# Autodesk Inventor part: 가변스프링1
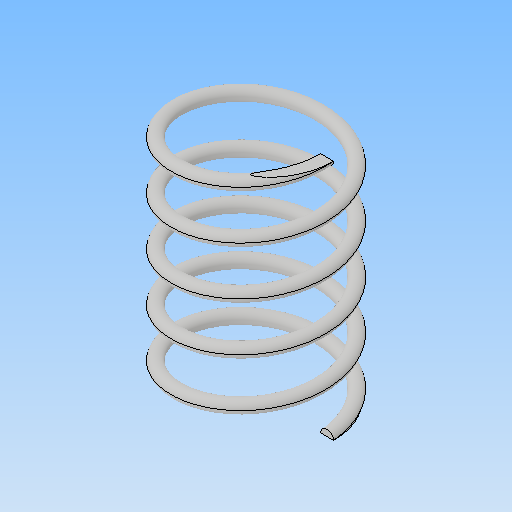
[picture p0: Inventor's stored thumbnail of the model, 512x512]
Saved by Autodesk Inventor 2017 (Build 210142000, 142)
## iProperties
Part Number: 가변스프링1
Material: 일반
Document SubType Name: Modeling
Designer: MRC
Density: 1 g/cm^3
Appearance: 기본값
Mass: 1.07319 g
Surface Area: 21.7273 cm^2
Volume: 1.07319 cm^3
Author: MRC
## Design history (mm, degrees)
sketch "스케치1"
  geometry: L1 (0, 0)-(0, 37.411); L2 (0, 0)-(11, 0); L3 (0, 37.411)-(11, 37.411); C1 r 1 at (11, 0)
  constraints: 6 end point, 2 horizontal, 1 centre point, 1 coincident, 1 vertical
  dimensions: "d0" = 37.4112 distance of L1.start L1.end (derived); "d1" = 11 distance of L1.end L3.end; "d2" = 11 distance of L1.start L2.end; "d3" = 2 diameter of C1
feature "코일1" sketch "스케치1" pitch "d4" = 10; turns "d6" = 5; dims "d5" = 37.4112 (= d0), "d7" = 0, angle "d8" = 90 deg, angle "d9" = 90 deg, "d10" = 0, "d11" = 0
sketch "스케치2"
  geometry: L1 (37.411, 15)-(0, 15); L2 (0, 15)-(0, -15); L3 (0, -15)-(37.411, -15); L4 (37.411, -15)-(37.411, 15); 2 further points
  constraints: 8 end point, 2 parallel, 1 coincident, 1 horizontal, 1 midpoint, 1 perpendicular
  dimensions: "d12" = 37.4112 distance of L2.end L3.end (= d0); "d13" = 30 distance of L3.end L1.start
extrude "돌출1" sketch "스케치2" stored distance "d14" = 0; taper "d15" = 0 deg
node "솔리드1"
